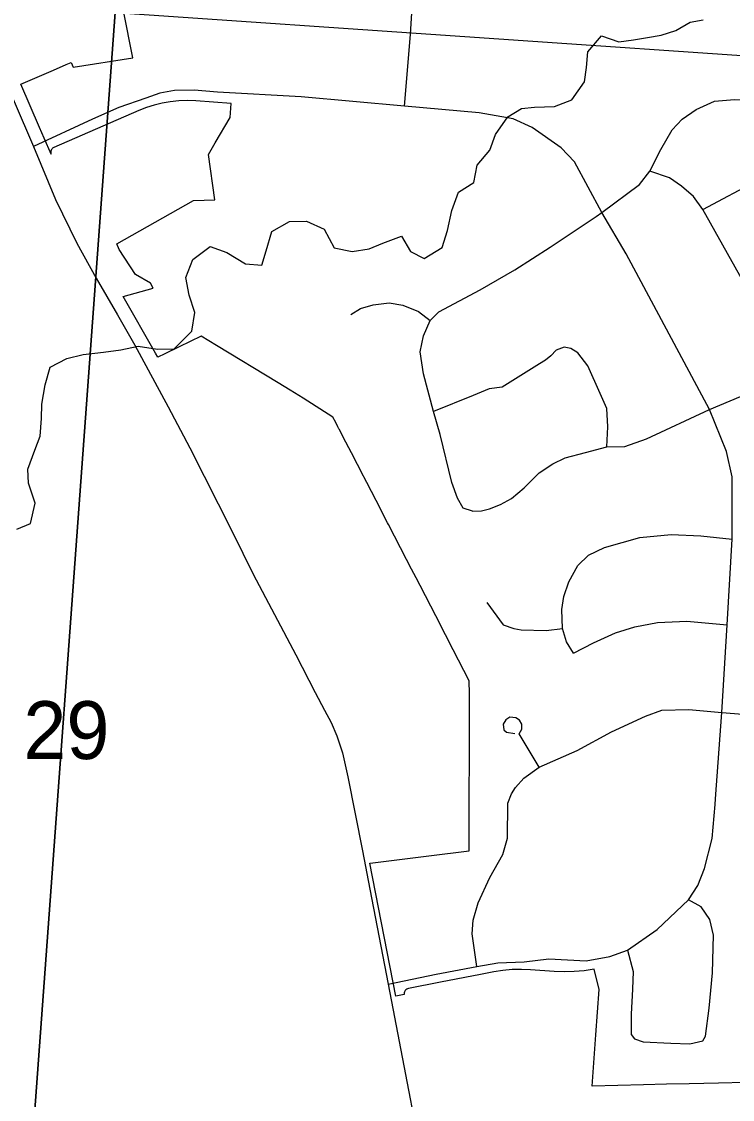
# Model space of a CAD drawing. Extents: x 0 to 34, y 0 to 22.
# Drawn here: x 3.682 to 4.196, y 16.45 to 17.23 of the extents above; entities that cross this region are included whole.
import ezdxf

# ---------------------------------------------------------------- set-up
doc = ezdxf.new("R2010")
doc.units = 0
for name, color, linetype in [('GM_X_Corporation', 7, 'Continuous'), ('GM_X_Minor_River', 7, 'Continuous'), ('GM_X_Section_Text', 7, 'Continuous'), ('GM_X_State_Route', 7, 'Continuous'), ('GM_X_Township_Road', 7, 'Continuous')]:
    doc.layers.add(name, color=color, linetype=linetype)

msp = doc.modelspace()

# ---------------------------------------------------------------- linework, layer by layer
at = {"layer": 'GM_X_Corporation'}
for points in [[(3.2481, 17.26928), (3.74964, 17.23668), (3.67551, 16.22523), (3.17454, 16.25805)], [(3.74964, 17.23668), (4.25556, 17.20216), (4.18465, 16.19055), (3.67551, 16.22523)]]:
    msp.add_lwpolyline(points, close=True, dxfattribs=at)
msp.add_lwpolyline([(4.20549, 16.46254), (4.18607, 16.4622), (4.16481, 16.46168), (4.14834, 16.46127), (4.13186, 16.46086), (4.09469, 16.45994), (4.0973, 16.49701), (4.09846, 16.51346), (4.09964, 16.52989), (4.09599, 16.54455), (4.08884, 16.54348), (4.08164, 16.54286), (4.07441, 16.54269), (4.06718, 16.54298), (4.05011, 16.54419), (4.04343, 16.54444), (4.03674, 16.54426), (4.03008, 16.54363), (4.02348, 16.54258), (4.01375, 16.54069), (3.9848, 16.53508), (3.96169, 16.5306), (3.96105, 16.53041), (3.96046, 16.53012), (3.95993, 16.52974), (3.95947, 16.52926), (3.9591, 16.52872), (3.95883, 16.52811), (3.95867, 16.52747), (3.95862, 16.52681), (3.95868, 16.52616), (3.95497, 16.52544), (3.95265, 16.52499), (3.93382, 16.6213), (3.93603, 16.62158), (3.93979, 16.62206), (3.97656, 16.62669), (4.0057, 16.63024), (4.00572, 16.65001), (4.00577, 16.67533), (4.00579, 16.69268), (4.00582, 16.70257), (4.00584, 16.71204), (4.00591, 16.74389), (4.00575, 16.75328), (3.99418, 16.77565), (3.98857, 16.78651), (3.98142, 16.80034), (3.97783, 16.80729), (3.97018, 16.82209), (3.96723, 16.82782), (3.96403, 16.83399), (3.9604, 16.84101), (3.94728, 16.86641), (3.94664, 16.86764), (3.93838, 16.88363), (3.93163, 16.89669), (3.92947, 16.90087), (3.92925, 16.90129), (3.92057, 16.91811), (3.91463, 16.92958), (3.91186, 16.93494), (3.91149, 16.93565), (3.91076, 16.93707), (3.90913, 16.94022), (3.90713, 16.94409), (3.88554, 16.95762), (3.87612, 16.96352), (3.86755, 16.96889), (3.82282, 16.99595), (3.8118, 17.00261), (3.79593, 16.99485), (3.78541, 16.9897), (3.78042, 16.98733), (3.77873, 16.9903), (3.75542, 17.0314), (3.7771, 17.03736), (3.77509, 17.04105), (3.76432, 17.04731), (3.75236, 17.06535), (3.7509, 17.06932), (3.80633, 17.10082), (3.82169, 17.10121), (3.81721, 17.13415), (3.82201, 17.14237), (3.83275, 17.16076), (3.83349, 17.171), (3.80799, 17.17285), (3.8018, 17.17307), (3.79561, 17.17286), (3.78945, 17.17221), (3.7836, 17.17119), (3.77783, 17.16978), (3.77217, 17.16798), (3.76664, 17.16581), (3.70532, 17.13916), (3.7048, 17.13888), (3.70432, 17.13853), (3.70391, 17.1381), (3.70357, 17.13761), (3.70331, 17.13708), (3.70314, 17.13651), (3.70305, 17.13592), (3.70306, 17.13533), (3.70317, 17.13474), (3.70336, 17.13418), (3.69486, 17.15361), (3.68127, 17.18482), (3.70495, 17.19512), (3.70499, 17.19513), (3.71425, 17.19916), (3.71775, 17.20067), (3.71922, 17.1973), (3.76233, 17.20389), (3.7557, 17.23797)], dxfattribs=at)
at = {"layer": 'GM_X_Minor_River'}
msp.add_lwpolyline([(3.67849, 16.86289), (3.68839, 16.86693), (3.69163, 16.88169), (3.68691, 16.89618), (3.6863, 16.90644), (3.69141, 16.92003), (3.69534, 16.93023), (3.69628, 16.94312), (3.69643, 16.95337), (3.6989, 16.96738), (3.70249, 16.98024), (3.71469, 16.98652), (3.72646, 16.98939), (3.74124, 16.99108), (3.75376, 16.99281), (3.76628, 16.99529), (3.78025, 16.9932), (3.79237, 16.99341), (3.80504, 17.00614), (3.80712, 17.01978), (3.80314, 17.03236), (3.80067, 17.04492), (3.80578, 17.05814), (3.8184, 17.06745), (3.83045, 17.06311), (3.84395, 17.05495), (3.85567, 17.05403), (3.85885, 17.06424), (3.86283, 17.07823), (3.8758, 17.08564), (3.88792, 17.08585), (3.9007, 17.07998), (3.90808, 17.06659), (3.9209, 17.06376), (3.93342, 17.06586), (3.94332, 17.0699), (3.95664, 17.07503), (3.96329, 17.06393), (3.97306, 17.05886), (3.98604, 17.06665), (3.99, 17.07913), (3.99323, 17.0935), (3.99796, 17.10673), (4.00903, 17.11378), (4.01148, 17.12628), (4.02072, 17.13716), (4.02467, 17.14849), (4.03355, 17.16127), (4.04348, 17.16721), (4.05295, 17.16822), (4.06734, 17.16878), (4.0799, 17.17354), (4.08917, 17.1867), (4.09045, 17.19693), (4.09137, 17.20831), (4.10137, 17.21993), (4.1138, 17.21559), (4.12442, 17.21696), (4.13466, 17.21871), (4.14452, 17.22048), (4.15517, 17.22374), (4.16547, 17.22968), (4.17495, 17.23144)], dxfattribs=at)
at = {"layer": 'GM_X_State_Route'}
msp.add_lwpolyline([(3.66163, 17.20652), (3.69056, 17.13978), (3.7064, 17.10156), (3.72182, 17.06988), (3.73576, 17.04454), (3.75117, 17.01814), (3.76384, 16.99618), (3.788, 16.95146), (3.80355, 16.92185), (3.83437, 16.86082), (3.84937, 16.83041), (3.8802, 16.77212), (3.89435, 16.74467), (3.90111, 16.732), (3.90576, 16.72313), (3.90998, 16.71342), (3.91399, 16.70116), (3.91779, 16.68364), (3.92856, 16.63021), (3.93371, 16.60246), (3.94702, 16.53379), (3.9801, 16.36165)], dxfattribs=at)
at = {"layer": 'GM_X_Township_Road'}
for points in [[(3.95889, 17.16901), (3.96332, 17.22077), (3.96502, 17.24827)], [(4.18389, 16.6678), (4.18838, 16.73028), (4.19228, 16.79369), (4.19592, 16.85571), (4.19601, 16.90083), (4.19174, 16.91918), (4.17957, 16.94953), (4.11922, 17.06215), (4.10173, 17.09196), (4.08183, 17.12875), (4.0721, 17.13892), (4.05123, 17.15356), (4.03739, 17.1599), (4.01284, 17.16413), (3.95889, 17.16901), (3.88416, 17.17564), (3.82358, 17.17918), (3.80663, 17.18067), (3.79256, 17.18023), (3.78197, 17.17832), (3.77171, 17.1749), (3.7522, 17.16802), (3.73313, 17.1596), (3.69056, 17.13978)], [(4.09755, 17.08918), (4.10173, 17.09196), (4.12879, 17.1124), (4.13631, 17.1219), (4.14422, 17.13773), (4.15253, 17.15198), (4.15966, 17.1595), (4.16995, 17.16663), (4.183, 17.17257), (4.19764, 17.17375), (4.22178, 17.17257), (4.2467, 17.17019), (4.30289, 17.16623), (4.34998, 17.16228), (4.41131, 17.15832)], [(4.17469, 17.09419), (4.21545, 17.11596), (4.23206, 17.12704), (4.24038, 17.13575), (4.24473, 17.14565), (4.2467, 17.17019)], [(4.23892, 16.97984), (4.20703, 17.03661), (4.17469, 17.09419), (4.16796, 17.10369), (4.15926, 17.11121), (4.15055, 17.11715), (4.13631, 17.1219)], [(4.00806, 16.87601), (4.00132, 16.87818), (3.99723, 16.88541), (3.99313, 16.89673), (3.98471, 16.93141), (3.97989, 16.94803), (3.97267, 16.97526), (3.97026, 16.99128), (3.97267, 17.00284), (3.97748, 17.01392), (3.98375, 17.02018), (4.0136, 17.03608), (4.03864, 17.05054), (4.06416, 17.06691), (4.09755, 17.08918)], [(4.00806, 16.87601), (4.01457, 16.87625), (4.02034, 16.8777), (4.02829, 16.88083), (4.03623, 16.88517), (4.04539, 16.89288), (4.05622, 16.90371), (4.06609, 16.91022), (4.075, 16.91455), (4.08968, 16.91841), (4.10534, 16.9225), (4.11833, 16.92274), (4.13399, 16.92829), (4.17957, 16.94953), (4.21691, 16.96527), (4.23892, 16.97984), (4.28904, 17.01541), (4.30606, 17.02451), (4.32426, 17.03164), (4.34206, 17.03718), (4.35948, 17.04193), (4.3757, 17.04312), (4.4038, 17.04233)], [(3.91996, 17.01821), (3.92696, 17.0227), (3.93632, 17.02523), (3.94781, 17.02659), (3.95774, 17.02503), (3.96904, 17.02036), (3.97748, 17.01392)], [(4.10534, 16.9225), (4.10606, 16.93696), (4.10534, 16.9502), (4.10052, 16.96105), (4.09137, 16.98104), (4.08415, 16.99043), (4.07909, 16.99356), (4.07427, 16.99453), (4.06849, 16.99236), (4.06474, 16.98839), (4.06082, 16.98525), (4.05646, 16.98248), (4.02949, 16.96562), (4.0201, 16.96442), (4.00854, 16.9596), (3.97989, 16.94803)], [(4.08116, 16.77327), (4.0761, 16.78148), (4.07321, 16.79101), (4.07263, 16.80487), (4.07408, 16.81412), (4.07783, 16.8248), (4.08418, 16.83665), (4.09198, 16.84415), (4.10353, 16.84964), (4.12922, 16.85687), (4.15175, 16.85917), (4.17311, 16.85802), (4.19592, 16.85571)], [(4.01836, 16.80978), (4.03019, 16.79361), (4.03799, 16.79101), (4.04319, 16.79014), (4.06137, 16.78956), (4.07321, 16.79101)], [(4.08116, 16.77327), (4.09548, 16.78066), (4.11154, 16.78804), (4.12544, 16.79238), (4.14193, 16.79542), (4.1632, 16.79629), (4.19228, 16.79369)], [(4.05625, 16.69079), (4.08376, 16.70292), (4.1085, 16.71638), (4.13325, 16.72768), (4.14497, 16.73201), (4.1645, 16.73245), (4.18838, 16.73028), (4.25219, 16.7253), (4.31146, 16.72067), (4.38068, 16.71659), (4.42102, 16.71337)], [(4.05625, 16.69079), (4.04183, 16.71478), (4.04384, 16.71814), (4.04384, 16.72182), (4.04216, 16.72468), (4.03948, 16.72635), (4.03512, 16.72686), (4.0321, 16.72501), (4.03026, 16.72182), (4.03076, 16.71764), (4.03277, 16.71595), (4.03864, 16.71511)], [(4.01127, 16.54659), (4.00787, 16.57016), (4.00846, 16.58016), (4.01215, 16.59258), (4.02054, 16.61103), (4.02993, 16.62747), (4.03328, 16.63929), (4.03361, 16.66463), (4.03629, 16.67134), (4.03915, 16.67604), (4.04518, 16.68274), (4.05625, 16.69079)], [(3.94702, 16.53379), (3.98189, 16.54097), (4.01127, 16.54659), (4.02631, 16.54913), (4.04533, 16.55), (4.06335, 16.55197), (4.09017, 16.5506), (4.10745, 16.55379), (4.12019, 16.55834), (4.14155, 16.57335), (4.16429, 16.59473), (4.17101, 16.60521), (4.17579, 16.61737), (4.18143, 16.63908), (4.1836, 16.66384), (4.18389, 16.6678)], [(4.12019, 16.55834), (4.12428, 16.54286), (4.12382, 16.53013), (4.12291, 16.51193), (4.12291, 16.49738), (4.12519, 16.49419), (4.13155, 16.49192), (4.15156, 16.491), (4.1652, 16.49055), (4.17475, 16.49282), (4.17657, 16.49601), (4.1793, 16.51648), (4.18157, 16.54196), (4.18248, 16.56925), (4.17976, 16.58062), (4.17339, 16.58973), (4.16429, 16.59473)]]:
    msp.add_lwpolyline(points, dxfattribs=at)

# ---------------------------------------------------------------- texts
at = {"layer": 'GM_X_Section_Text'}
msp.add_text('29', height=0.041856, rotation=0.00001, dxfattribs=at).set_placement((3.68317, 16.69661))

doc.saveas('drawing.dxf')
